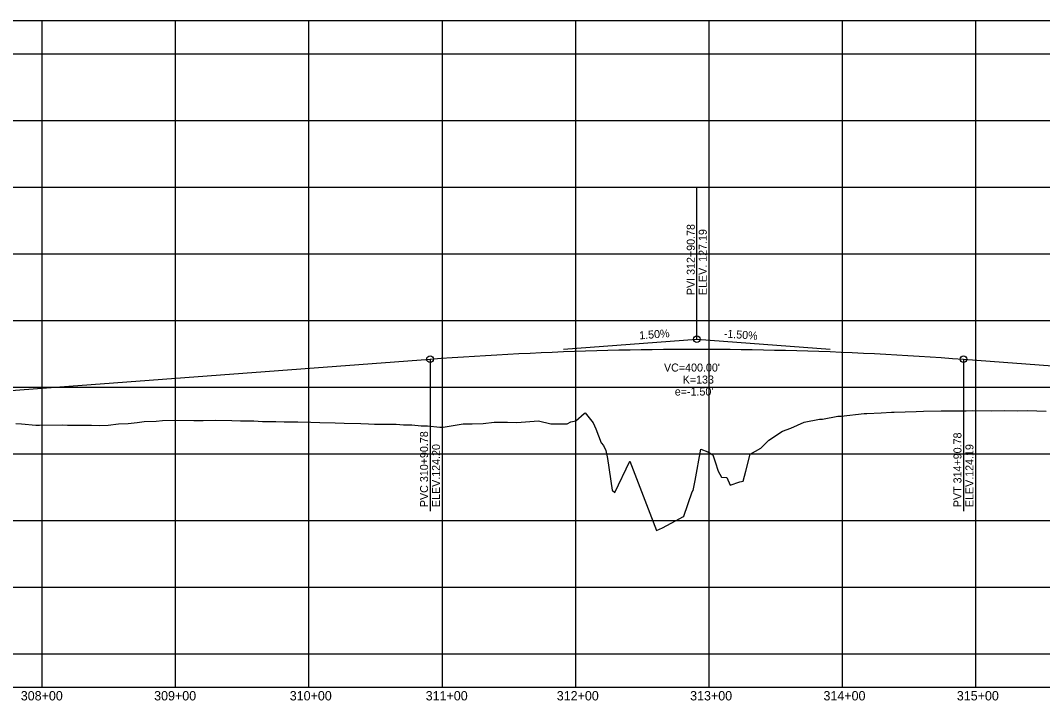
# Model space of a CAD drawing. Extents: x 1191541 to 1200065, y 1475807 to 1480451.
# Drawn here: x 1194690 to 1195456, y 1479932 to 1480443 of the extents above; entities that cross this region are included whole.
import ezdxf

# ---------------------------------------------------------------- set-up
doc = ezdxf.new("R2010")
doc.units = 0
for name, color, linetype in [('R_Exist Surface', 7, 'Continuous'), ('R_Grid', 7, 'Continuous'), ('R_Proposed Const Limits_Hand', 7, 'Continuous'), ('R_Vert Alg', 7, 'Continuous'), ('R_Vert Alg Annot', 7, 'Continuous'), ('R_Water', 7, 'Continuous')]:
    doc.layers.add(name, color=color, linetype=linetype)

msp = doc.modelspace()

# ---------------------------------------------------------------- linework, layer by layer
at = {"layer": 'R_Exist Surface'}
msp.add_lwpolyline([(1194686.52, 1480140.33), (1194690.78, 1480139.93), (1194701.49, 1480139.04), (1194704.34, 1480138.97), (1194721.18, 1480139.22), (1194725.21, 1480139.09), (1194730.28, 1480138.92), (1194743.27, 1480139.03), (1194749.4, 1480138.77), (1194755.73, 1480138.9), (1194763.43, 1480140.01), (1194770.8, 1480140.18), (1194777.5, 1480141.04), (1194782.75, 1480141.71), (1194791.59, 1480141.93), (1194796.39, 1480142.49), (1194805.69, 1480142.73), (1194820.01, 1480142.5), (1194826.92, 1480142.54), (1194835.97, 1480142.76), (1194848.43, 1480142.54), (1194854.99, 1480142.24), (1194864.92, 1480142.14), (1194871.35, 1480141.85), (1194881.4, 1480141.75), (1194887.72, 1480141.47), (1194897.87, 1480141.36), (1194907.79, 1480141.25), (1194914.34, 1480140.98), (1194925.87, 1480140.81), (1194932.64, 1480140.46), (1194945.16, 1480140.29), (1194950.89, 1480140.02), (1194955.34, 1480139.76), (1194963.91, 1480139.76), (1194971.63, 1480139.76), (1194977.1, 1480139.32), (1194983.45, 1480139.29), (1194990.56, 1480138.6), (1194995.09, 1480138.56), (1195004.46, 1480137.44), (1195006.92, 1480137.56), (1195021.95, 1480139.93), (1195028.79, 1480140.1), (1195036.92, 1480140.3), (1195045.06, 1480141.16), (1195055.06, 1480141.28), (1195062.17, 1480140.9), (1195078.44, 1480142.31), (1195087.8, 1480140.06), (1195099.81, 1480139.9), (1195102.75, 1480141.52), (1195106.32, 1480142.13), (1195112.74, 1480147.8), (1195113.45, 1480148.21), (1195119.46, 1480140.67), (1195121.44, 1480136.23), (1195125.5, 1480125.77), (1195127.19, 1480123.71), (1195129.03, 1480119.97), (1195130.2, 1480114), (1195133.77, 1480090.29), (1195135.68, 1480088.53), (1195146.82, 1480112.08), (1195146.88, 1480112.09), (1195146.96, 1480111.86), (1195167.02, 1480060.05), (1195171.43, 1480061.86), (1195184.34, 1480068.97), (1195186.77, 1480070.11), (1195187.3, 1480070.61), (1195193.75, 1480088.88), (1195194.37, 1480090.1), (1195195.81, 1480097.58), (1195200.19, 1480121.04), (1195205.43, 1480118.9), (1195209.27, 1480116.84), (1195210.91, 1480111.55), (1195213.12, 1480104.39), (1195215.73, 1480100), (1195219.68, 1480099.69), (1195222.19, 1480094.09), (1195229.43, 1480096.42), (1195231.9, 1480096.86), (1195233.8, 1480104.57), (1195237.19, 1480117.17), (1195245.17, 1480121.62), (1195251.2, 1480127.76), (1195261.4, 1480134.44), (1195267.61, 1480136.85), (1195277.74, 1480141.13), (1195289.13, 1480143.48), (1195291.52, 1480143.46), (1195302.92, 1480145.85), (1195305.3, 1480145.78), (1195322.67, 1480147.73), (1195324.54, 1480147.84), (1195335.32, 1480148.3), (1195343.25, 1480148.68), (1195345.16, 1480148.69), (1195361.71, 1480149.35), (1195367.17, 1480149.55), (1195380.45, 1480149.62), (1195385.03, 1480149.78), (1195399.04, 1480149.84), (1195403.59, 1480149.88), (1195418.22, 1480149.75), (1195427.88, 1480149.87), (1195437.34, 1480149.84), (1195445.01, 1480149.95), (1195459.12, 1480149.58)], dxfattribs=at)
at = {"layer": 'R_Grid'}
for p, q in [((1193906.32, 1480442.53), (1196406.32, 1480442.53)), ((1194706.32, 1479942.53), (1194706.32, 1480442.53)), ((1194806.32, 1479942.53), (1194806.32, 1480442.53)), ((1194906.32, 1479942.53), (1194906.32, 1480442.53)), ((1195006.32, 1479942.53), (1195006.32, 1480442.53)), ((1195106.32, 1479942.53), (1195106.32, 1480442.53)), ((1195206.32, 1479942.53), (1195206.32, 1480442.53)), ((1195306.32, 1479942.53), (1195306.32, 1480442.53)), ((1195406.32, 1479942.53), (1195406.32, 1480442.53)), ((1193906.32, 1480417.53), (1196406.32, 1480417.53)), ((1193906.32, 1480367.53), (1196406.32, 1480367.53)), ((1193906.32, 1480317.53), (1196406.32, 1480317.53)), ((1193906.32, 1480267.53), (1196406.32, 1480267.53)), ((1193906.32, 1480217.53), (1196406.32, 1480217.53)), ((1193906.32, 1480167.53), (1196406.32, 1480167.53)), ((1193906.32, 1480117.53), (1196406.32, 1480117.53)), ((1193906.32, 1480067.53), (1196406.32, 1480067.53)), ((1193906.32, 1480017.53), (1196406.32, 1480017.53)), ((1193906.32, 1479967.53), (1196406.32, 1479967.53))]:
    msp.add_line(p, q, dxfattribs=at)
at = {"layer": 'R_Vert Alg'}
for p, q in [((1195097.1, 1480196.01), (1195197.1, 1480203.5)), ((1195197.1, 1480203.5), (1195297.1, 1480195.99)), ((1194656.32, 1480163), (1194997.1, 1480188.52)), ((1195397.1, 1480188.48), (1195566.32, 1480175.77))]:
    msp.add_line(p, q, dxfattribs=at)
msp.add_lwpolyline([(1194997.1, 1480188.52), (1195005.44, 1480189.13), (1195013.77, 1480189.72), (1195022.1, 1480190.28), (1195030.44, 1480190.81), (1195038.77, 1480191.32), (1195047.1, 1480191.8), (1195055.44, 1480192.25), (1195063.77, 1480192.68), (1195072.1, 1480193.08), (1195080.44, 1480193.46), (1195088.77, 1480193.81), (1195097.1, 1480194.13), (1195105.44, 1480194.43), (1195113.77, 1480194.7), (1195122.1, 1480194.95), (1195130.44, 1480195.17), (1195138.77, 1480195.37), (1195147.1, 1480195.53), (1195155.44, 1480195.68), (1195163.77, 1480195.79), (1195172.1, 1480195.88), (1195180.44, 1480195.95), (1195188.77, 1480195.99), (1195205.44, 1480195.98), (1195213.77, 1480195.94), (1195222.1, 1480195.88), (1195230.44, 1480195.79), (1195238.77, 1480195.67), (1195247.1, 1480195.52), (1195255.44, 1480195.35), (1195263.77, 1480195.16), (1195272.1, 1480194.93), (1195280.44, 1480194.69), (1195288.77, 1480194.41), (1195297.1, 1480194.11), (1195305.44, 1480193.78), (1195313.77, 1480193.43), (1195322.1, 1480193.05), (1195330.44, 1480192.65), (1195338.77, 1480192.22), (1195347.1, 1480191.76), (1195355.44, 1480191.28), (1195363.77, 1480190.77), (1195372.1, 1480190.24), (1195380.44, 1480189.68), (1195388.77, 1480189.09), (1195397.1, 1480188.48)], dxfattribs=at)
at = {"layer": 'R_Vert Alg Annot'}
for p, q in [((1195197.1, 1480233.5), (1195197.1, 1480317.5)), ((1195197.1, 1480203.5), (1195197.1, 1480233.5)), ((1194997.1, 1480188.52), (1194997.1, 1480158.52)), ((1195397.1, 1480188.48), (1195397.1, 1480158.48)), ((1194997.1, 1480158.52), (1194997.1, 1480074.52)), ((1195397.1, 1480158.48), (1195397.1, 1480074.48))]:
    msp.add_line(p, q, dxfattribs=at)
for centre in [(1195197.1, 1480203.5), (1194997.1, 1480188.52), (1195397.1, 1480188.48)]:
    msp.add_circle(centre, 2.5, dxfattribs=at)
at = {"layer": 'R_Water'}
msp.add_line((1193906.32, 1479942.53), (1196406.32, 1479942.53), dxfattribs=at)

# ---------------------------------------------------------------- texts
at = {"layer": 'R_Proposed Const Limits_Hand'}
for s, p in [('308+00', (1194690.19, 1479932.53)), ('309+00', (1194790.19, 1479932.53)), ('310+00', (1194891.89, 1479932.53)), ('311+00', (1194993.83, 1479932.53)), ('312+00', (1195092.13, 1479932.53)), ('313+00', (1195192.13, 1479932.53)), ('314+00', (1195292.13, 1479932.53)), ('315+00', (1195392.13, 1479932.53))]:
    msp.add_text(s, height=7, dxfattribs=at).set_placement(p)
at = {"layer": 'R_Vert Alg Annot'}
for s, rotation, p in [('PVI 312+90.78', 90, (1195195.6, 1480236.5)), ('ELEV. 127.19', 90, (1195204.6, 1480236.5)), ('1.50%', 4.28235, (1195154.18, 1480203.3)), ('-1.50%', 355.70485, (1195217.18, 1480204.82)), ('PVC 310+90.78', 90, (1194995.6, 1480077.52)), ('PVT 314+90.78', 90, (1195395.6, 1480077.48)), ('ELEV.124.20', 90, (1195004.6, 1480077.52)), ('ELEV.124.19', 90, (1195404.6, 1480077.48))]:
    msp.add_text(s, height=6, rotation=rotation, dxfattribs=at).set_placement(p)
for s, p in [("VC=400.00'", (1195172.54, 1480179.19)), ('K=133', (1195186.57, 1480170.19)), ("e=-1.50'", (1195180.62, 1480161.19))]:
    msp.add_text(s, height=6, dxfattribs=at).set_placement(p)

doc.saveas('drawing.dxf')
